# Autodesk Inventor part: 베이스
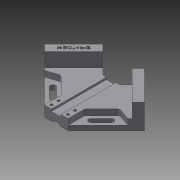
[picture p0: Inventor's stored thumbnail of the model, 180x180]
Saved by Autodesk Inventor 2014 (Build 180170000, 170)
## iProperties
Created: 2019-04
Part Number: 베이스
Material: Generic
Document SubType Name: Modeling
Designer: kh
Density: 1 g/cm^3
Appearance: Default
Mass: 222.781 g
Surface Area: 426.536 cm^2
Volume: 222.781 cm^3
Author: kh
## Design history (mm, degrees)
sketch "Sketch1"
  geometry: L1 (0, 84.853)-(84.853, 0); L2 (84.853, 0)-(20, -64.853); L3 (-20, -64.853)-(-84.853, 0); L4 (-84.853, 0)-(0, 84.853); L5 (0, 84.853)-(0, -84.853); L6 (84.853, 0)-(-84.853, 0); L7 (0, 84.853)-(35.355, 49.497); L8 (35.355, 49.497)-(14.005, 28.147); L9 (-14.005, 28.147)-(-35.355, 49.497); L10 (-35.355, 49.497)-(0, 84.853); L11 (-20, -64.853)-(20, -64.853); L12 (14.005, 28.147)-(-14.005, 28.147); 1 further point
  constraints: 24 end point, 5 parallel, 5 perpendicular, 2 midpoint, 1 horizontal, 1 point on line
  dimensions: "d0" = 120 distance of L5.end L3.end; "d1" = 120 distance of L1.end L5.end; "d4" = 40 distance of L2.end L3.start; "d5" = 50 distance between parallel lines of L4 L8; "d6" = 93 distance between parallel lines of L11 L12
extrude "Extrusion1" new body sketch "Sketch1" distance "d7" = 18; taper "d8" = 0 deg
sketch "Sketch2"
  geometry: L1 (-35.355, 49.497)-(-84.853, 0) reference; L2 (-35.355, 49.497)-(-24.749, 38.891); L3 (-24.749, 38.891)-(-74.246, -10.607); L4 (-74.246, -10.607)-(-84.853, 0); L5 (-84.853, 0)-(-35.355, 49.497); 1 further point
  constraints: 8 end point, 2 parallel, 2 point on line, 1 perpendicular
  dimensions: "d9" = 15 distance of L3.end L4.end
extrude "Extrusion2" join sketch "Sketch2" distance "d10" = 24; taper "d11" = 0 deg
sketch "Sketch3"
  geometry: L1 (-84.853, 0)-(-20, -64.853) reference; L2 (-70.711, -14.142)-(-49.497, -7.071); L3 (-49.497, -7.071)-(-20, -36.569); L4 (-20, -36.569)-(-20, -64.853); L5 (-20, -64.853)-(20, -64.853) reference; L6 (0, 0)-(0, -64.853); L7 (-35.355, 49.497)-(-84.853, 0) reference; 1 further point
  constraints: 8 end point, 2 parallel, 1 midpoint, 1 point on line
  dimensions: "d12" = 20 distance between parallel lines of L1 L3; "d46" = 20 distance from line of L7 L2.start; "d47" = 30 distance from line of L7 L2.end
extrude "Extrusion3" cut sketch "Sketch3" distance "d15" = 10; taper "d16" = 0 deg
sketch "Sketch4"
  geometry: L1 (-49.497, -21.213)-(-32.527, -38.184); L2 (-52.679, -24.395)-(-35.709, -41.366); L3 (-29.345, -35.002)-(-46.315, -18.031); L4 (-20, -64.853)-(-70.711, -14.142) reference; L5 (-35.355, 49.497)-(-84.853, 0) reference; A1 r 4.5 centre (-49.497, -21.213) between (-46.315, -18.031) and (-52.679, -24.395); A2 r 4.5 centre (-32.527, -38.184) between (-35.709, -41.366) and (-29.345, -35.002); 2 further points
  constraints: 8 end point, 4 point on circle, 4 tangent, 2 centre point, 1 midpoint, 1 parallel
  dimensions: "d17" = 10 distance between parallel lines of L4 L1; "d18" = 4.5 radius of A2; "d19" = 24 distance of L2.start L2.end; "d48" = 40 distance from line of L2.start L5
extrude "Extrusion4" cut sketch "Sketch4" stored distance "d21" = 0; taper "d22" = 0 deg
sketch "Sketch5"
  geometry: L1 (0, 9.914)-(0, -64.853); L2 (14, -46.853)-(14, -58.853); L3 (20, -64.853)-(-20, -64.853) reference; 2 further points
  constraints: 4 end point, 2 coincident, 1 midpoint, 1 parallel, 1 perpendicular
  dimensions: "d25" = 12 distance of L2.start L2.end; "d26" = 6 distance from line of L3 point (14, -58.853); "d27" = 14 distance from line of L1 point (14, -58.853)
hole "Hole1" sketch "Sketch5" at (14, -46.853), (14, -58.853) diameter "d28" = 4.5; stored, may be unused: countersink angle "d32" = 90 deg, drill point angle "d34" = 118 deg; dims "d29" = 6, "d30" = 8, "d31" = 10, "d33" = 8
fillet "Fillet1" dims "d49" = 5
workplane "Work Plane1"
mirror "Mirror1"
sketch "Sketch6"
  geometry: L1 (0, 18)-(-40, 18) reference; L2 (-40, 18)-(-40, 10) reference; L3 (0, 0)-(-40, 0) reference; L4 (0, 10)-(0, 0) reference; L5 (0, 18)-(0, 10) reference; L6 (-12, 0)-(-28, 0); L7 (-28, 0)-(-28, 3.5); L8 (-28, 3.5)-(-12, 3.5); L9 (-12, 3.5)-(-12, 0); L10 (-14, 15)-(-26, 15); L11 (-26, 15)-(-26, 18); L12 (-26, 18)-(-14, 18); L13 (-14, 18)-(-14, 15); L14 (-40, 10)-(-40, 0) reference; 3 further points
  constraints: 16 end point, 4 midpoint, 4 parallel, 2 horizontal, 2 perpendicular
  dimensions: "d36" = 16 distance of L6.start L6.end; "d37" = 12 distance of L11.end L12.end; "d38" = 3.5 distance of L6.end L7.end; "d39" = 3 distance of L10.end L11.end
extrude "Extrusion5" cut sketch "Sketch6" stored distance "d40" = 10; taper "d41" = 0 deg
sketch "Sketch7"
  geometry: L1 (-28.998, 37.123)-(-72.478, -6.358); L2 (-72.478, -6.358)-(-80.604, 1.768); L3 (-80.604, 1.768)-(-37.123, 45.249); L4 (-37.123, 45.249)-(-28.998, 37.123); L5 (-35.355, 49.497)-(-30.052, 44.194); L6 (-30.052, 44.194)-(-54.801, 19.445); L7 (-54.801, 19.445)-(-60.104, 24.749); L8 (-60.104, 24.749)-(-35.355, 49.497); L9 (-28.998, 37.123)-(-80.604, 1.768); L10 (-35.355, 49.497)-(-84.853, 0) reference; 1 further point
  constraints: 10 end point, 3 parallel, 2 midpoint, 1 coincident, 1 perpendicular, 2 other
  dimensions: "d42" = 7.5 distance of L6.end L7.end; "d43" = 35 distance of L5.end L6.end
emboss "Emboss1" sketch "Sketch7" dims "d1" = 120, "d44" = 0.5, "d45" = 0
body "Solid1"
node "Projected Loop1"
